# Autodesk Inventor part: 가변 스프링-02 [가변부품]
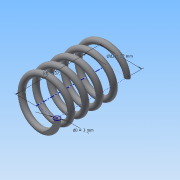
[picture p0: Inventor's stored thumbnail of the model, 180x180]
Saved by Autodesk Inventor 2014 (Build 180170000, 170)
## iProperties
Created: 2015-09
Part Number: 가변 스프링-02 [가변부품]
Material: 강철, 탄소
Document SubType Name: Modeling
Designer: study
Density: 7.87 g/cm^3
Appearance: 반연마
Mass: 18.8856 g
Surface Area: 32.5491 cm^2
Volume: 2.3997 cm^3
Author: study
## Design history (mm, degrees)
sketch "스케치1"
  geometry: L1 (0, 0)-(11, 0); L2 (11, 0)-(11, 36.411); L3 (11, 36.411)-(0, 36.411); L4 (0, 36.411)-(0, 0); C1 r 1.5 at (11, 0)
  constraints: 8 end point, 2 parallel, 1 centre point, 1 coincident, 1 horizontal, 1 perpendicular
  dimensions: "d0" = 3 diameter of C1; "d1" = 36.4112 distance of L3.end L1.start (derived); "d2" = 22 diameter of L2 L4
feature "코일1" sketch "스케치1" pitch "d3" = 10; turns "d5" = 5; dims "d4" = 36.4112 (= d1), "d6" = 0, angle "d7" = 90 deg, angle "d8" = 90 deg, "d9" = 0, "d10" = 0
sketch "스케치2"
  geometry: L1 (-12.5, 0)-(-9.5, 0) reference; 1 further point
  constraints: 1 horizontal alignment
extrude "돌출1" cut sketch "스케치2" stored distance "d11" = 10; taper "d12" = 0 deg
node "작업 평면1"
sketch "스케치3"
  geometry: L1 (-9.5, 0)-(-12.5, 0) reference; 1 further point
  constraints: 1 horizontal alignment
extrude "돌출2" cut sketch "스케치3" stored distance "d14" = 10; taper "d15" = 0 deg
node "솔리드1"
node "절단 모서리 투영1"
node "절단 모서리 투영2"
other parameters: "d13" = 36.4112 (= d1)
